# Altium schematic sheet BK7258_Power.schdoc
size 290 x 144 mm
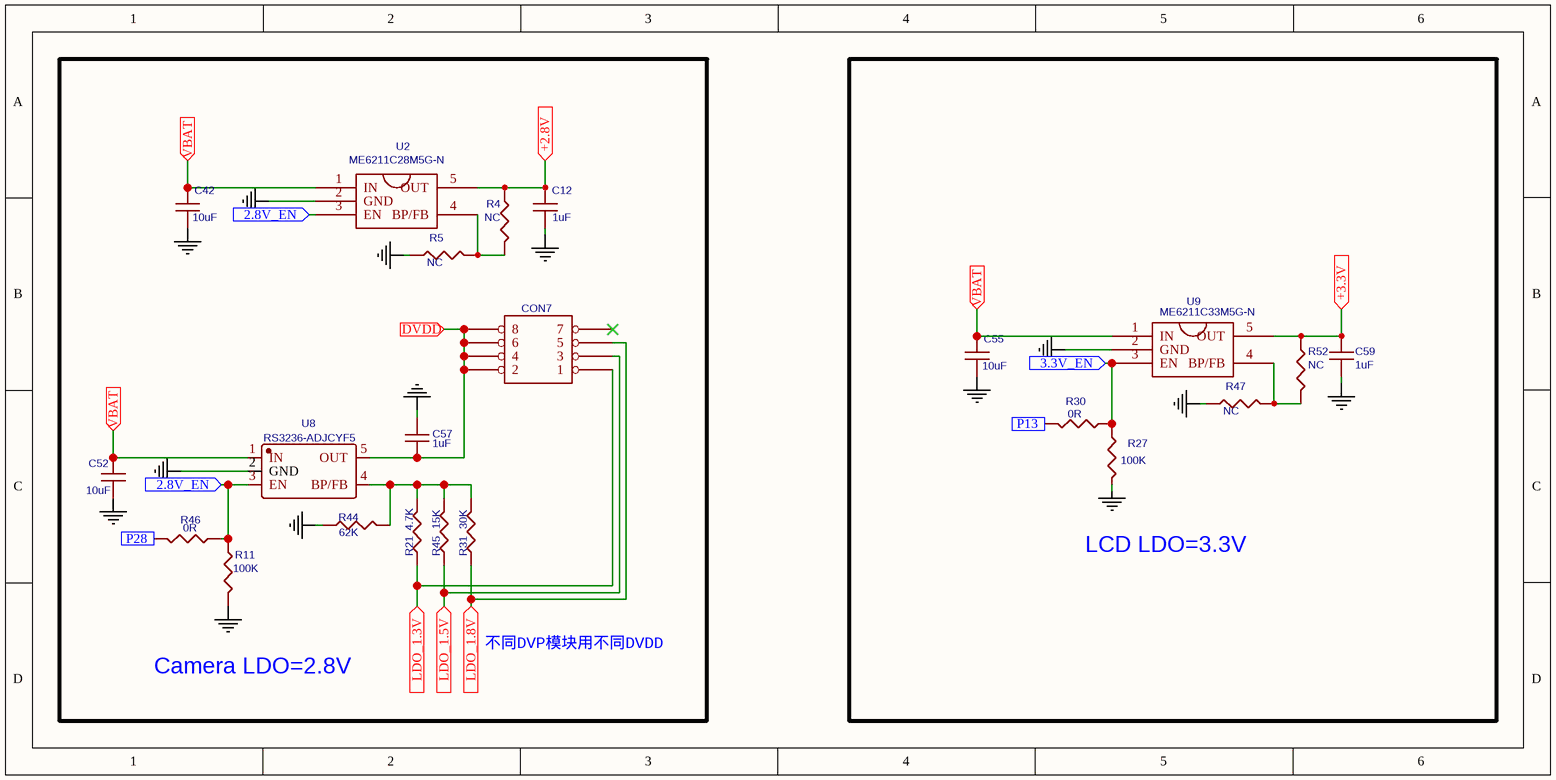
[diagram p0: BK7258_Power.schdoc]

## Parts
C12  1uF  [C0402]
C42  10uF  [C0603]
C52  10uF  [C0603]
C55  10uF  [C0603]
C57  1uF  [C0402]
C59  1uF  [C0402]
CON7  CON_2X4  [CON_2X4_2.54]  (value not drawn)
R4  NC  [R0402]
R5  NC  [R0402]
R11  100K  [R0402]
R21  4.7K  [R0402]
R27  100K  [R0402]
R30  0R  [R0402]
R31  30K  [R0402]
R44  62K  [R0402]
R45  15K  [R0402]
R46  0R  [R0402]
R47  NC  [R0402]
R52  NC  [R0402]
U2  ME6211C28M5G-N  [SOT23-5_SGM2019]
U8  RS3236-ADJCYF5  [SOT23-5_SGM2019]
U9  ME6211C33M5G-N  [SOT23-5_SGM2019]

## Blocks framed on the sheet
Camera LDO=2.8V: C12 C42 C52 C57 CON7 R4 R5 R11 R21 R31 R44-R46 U2 U8
LCD LDO=3.3V: C55 C59 R27 R30 R47 R52 U9

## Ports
2.8V_EN (in), 3.3V_EN (in), +2.8V (in), +3.3V (in), DVDD (in), LDO_1.3V (in), LDO_1.5V (in), LDO_1.8V (in), P13 (in), P28 (in), VBAT (in)

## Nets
GGND: C12.2 C42.2 C52.2 C55.2 C57.2 C59.2 R5.1 R11.2 R27.2 R44.1 R47.1 U2.2(GND) U8.2(GND) U9.2(GND)
2.8V_EN: R11.1 R46.1 U2.3(EN) U8.3(EN) ; port 2.8V_EN
3.3V_EN: R27.1 R30.1 U9.3(EN) ; port 3.3V_EN
+2.8V: C12.1 R4.1 U2.5(OUT) ; port +2.8V
+3.3V: C59.1 R52.1 U9.5(OUT) ; port +3.3V
DVDD: C57.1 CON7.2 CON7.4 CON7.6 CON7.8 U8.5(OUT) ; port DVDD
LDO_1.3V: CON7.1 R21.1 ; port LDO_1.3V
LDO_1.5V: CON7.3 R45.1 ; port LDO_1.5V
LDO_1.8V: CON7.5 R31.1 ; port LDO_1.8V
P13: R30.2 ; port P13
P28: R46.2 ; port P28
VBAT: C42.1 C52.1 C55.1 U2.1(IN) U8.1(IN) U9.1(IN) ; port VBAT
NetR4_2: R4.2 R5.2 U2.4(BP/FB)
NetR21_2: R21.2 R31.2 R44.2 R45.2 U8.4(BP/FB)
NetR47_2: R47.2 R52.2 U9.4(BP/FB)

Not connected (* = marked no-connect by the designer): CON7 7*

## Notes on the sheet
- 不同DVP模块用不同DVDD

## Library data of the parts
C12 C57 C59 = 1uF: Manufacturer: AVX; Manufacturer Part Number: 06035C103KAt2A; APN: C006-0
C42 C52 C55 = 10uF: Manufacturer Part Number: 06035A101KAT2A; Manufacturer: AVX; APN: C029-0
CON7 = CON_2X4: Package Display: No
R4 R5 R47 R52 = NC: Manufacturer Part Number: RK73H2AT4752F; Manufacturer: KOA; APN: R096-0
R11 R27 = 100K: Manufacturer Part Number: RK73H2AT4752F; Manufacturer: KOA; APN: R096-0
R21 = 4.7K: Manufacturer Part Number: RK73H2AT4752F; Manufacturer: KOA; APN: R096-0
R30 R46 = 0R: Manufacturer Part Number: RK73H2AT4752F; Manufacturer: KOA; APN: R096-0
R31 = 30K: Manufacturer Part Number: RK73H2AT4752F; Manufacturer: KOA; APN: R096-0
R44 = 62K: Manufacturer Part Number: RK73H2AT4752F; Manufacturer: KOA; APN: R096-0
R45 = 15K: Manufacturer Part Number: RK73H2AT4752F; Manufacturer: KOA; APN: R096-0
U2 = ME6211C28M5G-N: APN: U531
U8 = RS3236-ADJCYF5: Manufacturer: RUNIC(润石); Contributor: LCSC
U9 = ME6211C33M5G-N: APN: U531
